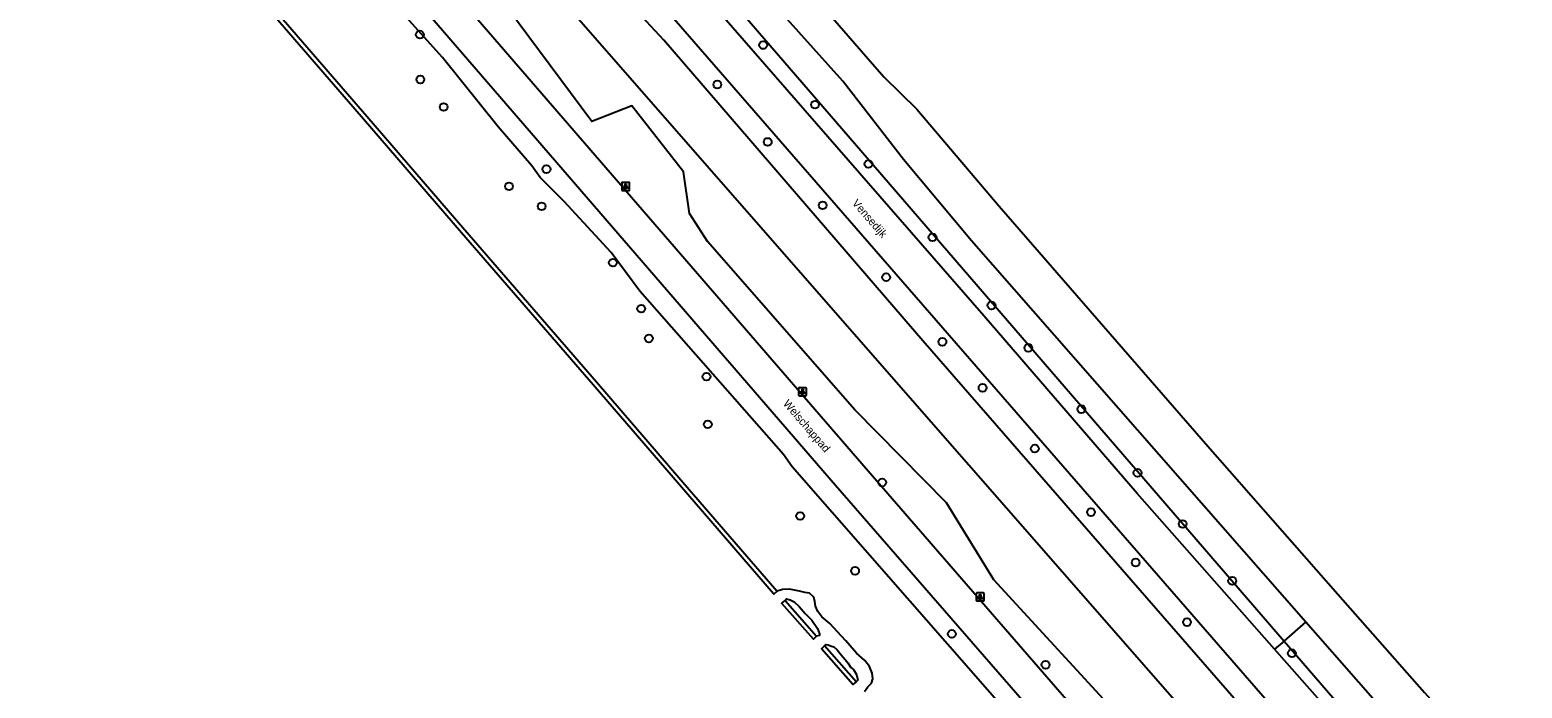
# Model space of a CAD drawing. Extents: x 155209 to 156823, y 385356 to 388482.
# Drawn here: x 155780.5 to 155966.9, y 385575.2 to 385657.3 of the extents above; entities that cross this region are included whole.
import ezdxf

# ---------------------------------------------------------------- set-up
doc = ezdxf.new("R2010")
doc.units = 0
for name, color, linetype in [('IMGEO_Berm_groen', 7, 'Continuous'), ('IMGEO_Boom', 7, 'Continuous'), ('IMGEO_Fietspad_gesloten', 7, 'Continuous'), ('IMGEO_Gemengd_bos', 7, 'Continuous'), ('IMGEO_Groenvoorziening', 7, 'Continuous'), ('IMGEO_Kademuur', 7, 'Continuous'), ('IMGEO_Lichtpunt', 7, 'Continuous'), ('IMGEO_Openbare_ruimte_label', 7, 'Continuous'), ('IMGEO_Rijbaan_lokaal_gesloten', 7, 'Continuous'), ('IMGEO_Waterloop', 7, 'Continuous')]:
    doc.layers.add(name, color=color, linetype=linetype)

msp = doc.modelspace()

# ---------------------------------------------------------------- linework, layer by layer
at = {"layer": 'IMGEO_Berm_groen'}
for points in [[(155959.32, 385541.34), (155930.14, 385574.84), (155892.08, 385618.52), (155859.69, 385656.07), (155852.69, 385663.67), (155827.38, 385692.36), (155816.07, 385705.59), (155791.34, 385733.72), (155787.45, 385737.87), (155780.5, 385745.88)], [(155845.61, 385686.83), (155855.07, 385676.14), (155886.95, 385639.23), (155937.21, 385581.04)], [(155952.7, 385530.17), (155950.59, 385532.09), (155946.03, 385544), (155926.93, 385565.21), (155922.9, 385568.46), (155921.66, 385569.46), (155917.45, 385570.69), (155900.94, 385588.67), (155895.02, 385598.3), (155883.59, 385609.91), (155865.17, 385630.9), (155862.9, 385634.42), (155862.16, 385639.6), (155855.72, 385647.87), (155850.73, 385645.9), (155838.97, 385661.71), (155833.46, 385670.65), (155827.75, 385672.6), (155823.98, 385678.66)], [(155972.92, 385492.24), (155965.33, 385500), (155913.21, 385559.93), (155900.15, 385574.95), (155875.73, 385602.78), (155874.64, 385604.33), (155856.72, 385624.72), (155853.11, 385629.55), (155847.26, 385635.93), (155844.26, 385638.91), (155843.23, 385640.36), (155839, 385645.25), (155832.07, 385653.89), (155824.14, 385662.7), (155814.49, 385673.96)], [(155937.21, 385581.04), (155936.02, 385580.01)], [(155937.21, 385581.04), (155969.69, 385543.44)]]:
    msp.add_lwpolyline(points, dxfattribs=at)
at = {"layer": 'IMGEO_Boom'}
for centre in [(155829.23, 385656.75), (155872.12, 385655.44), (155829.29, 385651.14), (155866.39, 385650.51), (155878.6, 385648), (155832.2, 385647.71), (155872.69, 385643.35), (155885.27, 385640.6), (155845.04, 385639.95), (155840.37, 385637.81), (155844.44, 385635.31), (155879.55, 385635.43), (155893.27, 385631.44), (155853.34, 385628.28), (155887.49, 385626.46), (155856.88, 385622.53), (155900.64, 385622.94), (155857.84, 385618.82), (155894.51, 385618.4), (155905.24, 385617.65), (155865.04, 385614.05), (155899.53, 385612.65), (155911.86, 385609.99), (155865.2, 385608.09), (155906.05, 385605.07), (155918.88, 385602.04), (155886.99, 385600.84), (155876.74, 385596.66), (155913.07, 385597.13), (155924.53, 385595.66), (155918.66, 385590.84), (155883.6, 385589.81), (155930.72, 385588.55), (155925.07, 385583.4), (155895.68, 385581.94), (155938.17, 385579.52), (155907.4, 385578.08)]:
    msp.add_circle(centre, 0.489, dxfattribs=at)
at = {"layer": 'IMGEO_Fietspad_gesloten'}
for points in [[(155801.14, 385693.08), (155881.17, 385600.52), (155915.04, 385561.54)], [(155918.18, 385564.31), (155885.24, 385602.25), (155815.7, 385682.65)]]:
    msp.add_lwpolyline(points, dxfattribs=at)
at = {"layer": 'IMGEO_Gemengd_bos'}
for points in [[(155851.78, 385692.17), (155887.19, 385651.49), (155891.3, 385647.45), (155901.59, 385635.34), (155927.68, 385605.37), (155943.93, 385586.89), (155954.72, 385574.62), (155959.07, 385569.83), (155978.29, 385550.24), (156000, 385528.73), (156022.52, 385506.16), (156028.35, 385500), (156035.27, 385492.31), (156040.08, 385486.06), (156043.32, 385480.72), (156046.43, 385475.88)], [(155939.92, 385583.4), (155898.13, 385630.99), (155889.67, 385641.14), (155882.05, 385650.94), (155865.58, 385669.32), (155861.07, 385674.68), (155848.14, 385689.39), (155847.34, 385690.32)], [(155937.21, 385581.04), (155939.92, 385583.4)], [(156000, 385516.89), (155949.78, 385572.17), (155939.92, 385583.4)]]:
    msp.add_lwpolyline(points, dxfattribs=at)
at = {"layer": 'IMGEO_Groenvoorziening'}
msp.add_lwpolyline([(155812.62, 385700.37), (155814.03, 385698.73), (155925.85, 385571.06), (155957.92, 385534.44)], dxfattribs=at)
at = {"layer": 'IMGEO_Kademuur'}
for points in [[(155873.85, 385587.28), (155873.44, 385586.91), (155873.4, 385586.95), (155861.67, 385600.54), (155850.89, 385613.03), (155834.42, 385632), (155822.18, 385646.19), (155808.53, 385662.01), (155799.42, 385672.56), (155793.17, 385679.8), (155793.59, 385680.16), (155794.93, 385678.6)], [(155795.79, 385677.61), (155799.84, 385672.92), (155808.94, 385662.37), (155822.6, 385646.55), (155834.83, 385632.36), (155851.31, 385613.39), (155862.09, 385600.89), (155873.82, 385587.31), (155873.85, 385587.28)], [(155878.8, 385581.65), (155878.39, 385581.29), (155874.45, 385585.75), (155874.43, 385585.77), (155874.86, 385586.12), (155874.86, 385586.11)], [(155874.86, 385586.11), (155878.8, 385581.65)], [(155883.73, 385575.96), (155883.31, 385575.6), (155879.39, 385580.09), (155879.8, 385580.45)], [(155883.73, 385575.96), (155879.8, 385580.45)]]:
    msp.add_lwpolyline(points, dxfattribs=at)
at = {"layer": 'IMGEO_Lichtpunt'}
for p, q in [((155854.44, 385638.2), (155854.44, 385637.39)), ((155854.44, 385638.2), (155854.44, 385637.39)), ((155855.34, 385638.29), (155854.53, 385638.29)), ((155855.34, 385638.29), (155854.53, 385638.29)), ((155854.53, 385637.3), (155855.34, 385637.3)), ((155854.53, 385637.3), (155855.34, 385637.3)), ((155855.43, 385637.39), (155855.43, 385638.2)), ((155855.43, 385637.39), (155855.43, 385638.2)), ((155876.54, 385612.58), (155876.54, 385611.77)), ((155876.54, 385612.58), (155876.54, 385611.77)), ((155877.44, 385612.67), (155876.64, 385612.67)), ((155877.44, 385612.67), (155876.64, 385612.67)), ((155876.64, 385611.67), (155877.44, 385611.67)), ((155876.64, 385611.67), (155877.44, 385611.67)), ((155877.54, 385611.77), (155877.54, 385612.58)), ((155877.54, 385611.77), (155877.54, 385612.58)), ((155898.72, 385586.95), (155898.72, 385586.14)), ((155898.72, 385586.95), (155898.72, 385586.14)), ((155899.62, 385587.05), (155898.82, 385587.05)), ((155899.62, 385587.05), (155898.82, 385587.05)), ((155899.72, 385586.14), (155899.72, 385586.95)), ((155899.72, 385586.14), (155899.72, 385586.95)), ((155898.82, 385586.05), (155899.62, 385586.05)), ((155898.82, 385586.05), (155899.62, 385586.05))]:
    msp.add_line(p, q, dxfattribs=at)
for points in [[(155854.81, 385637.86), (155854.85, 385637.83), (155854.66, 385637.57), (155854.62, 385637.6), (155854.81, 385637.86)], [(155854.91, 385637.81), (155854.96, 385637.81), (155854.96, 385637.49), (155854.91, 385637.49), (155854.91, 385637.81)], [(155855.02, 385637.83), (155855.06, 385637.86), (155855.25, 385637.6), (155855.21, 385637.57), (155855.02, 385637.83)], [(155876.92, 385612.24), (155876.96, 385612.21), (155876.77, 385611.95), (155876.73, 385611.98), (155876.92, 385612.24)], [(155877.02, 385612.19), (155877.07, 385612.19), (155877.07, 385611.87), (155877.02, 385611.87), (155877.02, 385612.19)], [(155877.13, 385612.21), (155877.17, 385612.24), (155877.35, 385611.98), (155877.32, 385611.95), (155877.13, 385612.21)], [(155899.1, 385586.61), (155899.13, 385586.59), (155898.95, 385586.32), (155898.91, 385586.35), (155899.1, 385586.61)], [(155899.2, 385586.57), (155899.25, 385586.57), (155899.25, 385586.24), (155899.2, 385586.24), (155899.2, 385586.57)], [(155899.31, 385586.59), (155899.35, 385586.61), (155899.53, 385586.35), (155899.49, 385586.32), (155899.31, 385586.59)]]:
    msp.add_lwpolyline(points, dxfattribs=at)
for centre in [(155854.94, 385638), (155877.04, 385612.37), (155899.22, 385586.75)]:
    msp.add_circle(centre, 0.0994, dxfattribs=at)
for centre, start, end in [((155854.53, 385638.2), 90, 180), ((155854.53, 385638.2), 90, 180), ((155854.53, 385637.39), 180, 270), ((155854.53, 385637.39), 180, 270), ((155855.34, 385638.2), 0, 90), ((155855.34, 385638.2), 0, 90), ((155855.34, 385637.39), 270, 0), ((155855.34, 385637.39), 270, 360), ((155876.64, 385612.58), 90, 180), ((155876.64, 385612.58), 90, 180), ((155876.64, 385611.77), 180, 270), ((155876.64, 385611.77), 180, 270), ((155877.44, 385612.58), 0, 90), ((155877.44, 385612.58), 0, 90), ((155877.44, 385611.77), 270, 0), ((155877.44, 385611.77), 270, 360), ((155898.82, 385586.95), 90, 180), ((155898.82, 385586.95), 90, 180), ((155899.62, 385586.95), 0, 90), ((155899.62, 385586.95), 0, 90), ((155898.82, 385586.14), 180, 270), ((155898.82, 385586.14), 180, 270), ((155899.62, 385586.14), 270, 0), ((155899.62, 385586.14), 270, 360)]:
    msp.add_arc(centre, 0.0946, start, end, dxfattribs=at)
at = {"layer": 'IMGEO_Rijbaan_lokaal_gesloten'}
for points in [[(155782.06, 385749.04), (155782.07, 385749.03), (155858.46, 385661.65), (155932.32, 385576.76), (155953.55, 385552.36)], [(155936.02, 385580.01), (155918.84, 385599.48), (155899.68, 385621.64), (155844.88, 385684.53)], [(155959.1, 385553.69), (155950.77, 385563.31), (155936.02, 385580.01)]]:
    msp.add_lwpolyline(points, dxfattribs=at)
at = {"layer": 'IMGEO_Waterloop'}
for points in [[(155884.79, 385574.73), (155885.19, 385575.31), (155885.64, 385575.78), (155885.83, 385576.32), (155885.72, 385577.03), (155885.4, 385577.85), (155884.83, 385578.62), (155883.79, 385579.55), (155882.43, 385581.08), (155881.42, 385582.18), (155880.43, 385583.22), (155879.46, 385584.05), (155878.96, 385584.73), (155878.66, 385585.39), (155878.58, 385585.98), (155878.44, 385586.54), (155877.89, 385587.03), (155877.31, 385587.09), (155876.67, 385587.28), (155875.39, 385587.5), (155874.52, 385587.49), (155873.85, 385587.28)], [(155874.86, 385586.11), (155875.03, 385586.3), (155875.5, 385586.18), (155875.99, 385585.95), (155876.61, 385585.34), (155877.37, 385584.47), (155878.18, 385583.64), (155878.89, 385582.62), (155879.16, 385581.93), (155879.16, 385581.74), (155878.8, 385581.65)], [(155879.8, 385580.45), (155880, 385580.63), (155880.23, 385580.59), (155880.54, 385580.45), (155880.96, 385580.32), (155881.36, 385579.94), (155881.85, 385579.34), (155882.35, 385578.72), (155882.71, 385578.31), (155883.09, 385577.74), (155883.4, 385577.49), (155883.77, 385576.85), (155883.96, 385576.18), (155883.73, 385575.96)]]:
    msp.add_lwpolyline(points, dxfattribs=at)

# ---------------------------------------------------------------- texts
at = {"layer": 'IMGEO_Openbare_ruimte_label'}
for s, rotation, p in [('Vensedijk', 310.9865, (155883.16, 385635.66)), ('Welschappad', 310.8249, (155874.54, 385610.64))]:
    msp.add_text(s, height=1, rotation=rotation, dxfattribs=at).set_placement(p)

doc.saveas('drawing.dxf')
